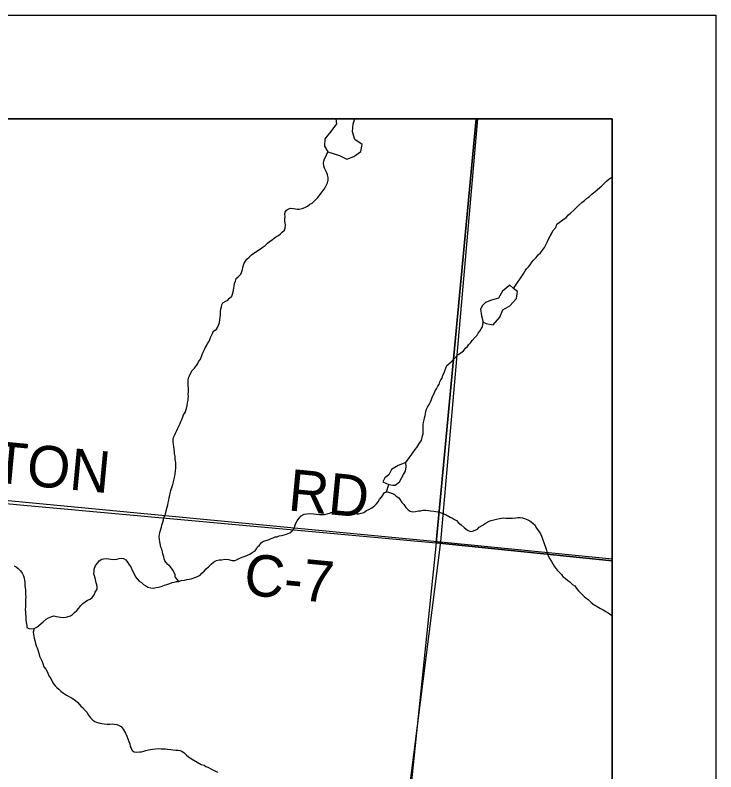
# Model space of a CAD drawing. Extents: x 0 to 34, y -4 to 22.
# Drawn here: x 8.324 to 9, y 20.27 to 21 of the extents above; entities that cross this region are included whole.
import ezdxf

# ---------------------------------------------------------------- set-up
doc = ezdxf.new("R2010")
doc.units = 0
for name, color, linetype in [('GM_X_County_Road', 7, 'Continuous'), ('GM_X_County_Road_Text', 7, 'Continuous'), ('GM_X_Minor_Lake', 7, 'Continuous'), ('GM_X_Minor_River', 7, 'Continuous'), ('GM_X_Section', 7, 'Continuous'), ('GM_X_Township_Road', 7, 'Continuous'), ('SH_Data', 7, 'Continuous'), ('SN_P_Text', 7, 'Continuous')]:
    doc.layers.add(name, color=color, linetype=linetype)

msp = doc.modelspace()

# ---------------------------------------------------------------- linework, layer by layer
at = {"layer": 'GM_X_County_Road'}
msp.add_lwpolyline([(7.2632, 20.63671), (7.3702, 20.62568), (7.41256, 20.62217), (7.42628, 20.62178), (7.44548, 20.62217), (7.45538, 20.62279), (7.4631, 20.62295), (7.47024, 20.62248), (7.47641, 20.62171), (7.48117, 20.62073), (7.4885, 20.61933), (7.50761, 20.61542), (7.52204, 20.61242), (7.53238, 20.61066), (7.54107, 20.60934), (7.55527, 20.60755), (7.58468, 20.60427), (7.63016, 20.59975), (7.68968, 20.59354), (7.69545, 20.59331), (7.82578, 20.57896), (8.73462, 20.49213), (8.9, 20.47558)], dxfattribs=at)
at = {"layer": 'GM_X_Minor_Lake'}
for points in [[(8.63343, 20.9), (8.63402, 20.89516), (8.62876, 20.88779), (8.62296, 20.8807), (8.62252, 20.87375), (8.62587, 20.86831)], [(8.62587, 20.86831), (8.63703, 20.86456), (8.64392, 20.86118), (8.65067, 20.8637), (8.65748, 20.86835), (8.65899, 20.87528), (8.65187, 20.88), (8.64965, 20.88755), (8.65009, 20.89504), (8.65172, 20.9)], [(8.80493, 20.73647), (8.80117, 20.73958), (8.79433, 20.73385), (8.79041, 20.72699), (8.78367, 20.72501), (8.77772, 20.72274)], [(8.7783, 20.70265), (8.78524, 20.70141), (8.79158, 20.70875), (8.79443, 20.71591), (8.80122, 20.7195), (8.80782, 20.72683), (8.80852, 20.73351), (8.80493, 20.73647)], [(8.77772, 20.72274), (8.77498, 20.72013), (8.77301, 20.71643), (8.77393, 20.70998), (8.77565, 20.70378), (8.7783, 20.70265)], [(8.68452, 20.5475), (8.68851, 20.5466), (8.69066, 20.54655), (8.69502, 20.54992), (8.69868, 20.55706), (8.70063, 20.56023), (8.70127, 20.56423), (8.70083, 20.56852), (8.69353, 20.56575), (8.68728, 20.56189), (8.68447, 20.5566), (8.68065, 20.55375)], [(8.68065, 20.55375), (8.67868, 20.54978), (8.68452, 20.5475)]]:
    msp.add_lwpolyline(points, dxfattribs=at)
at = {"layer": 'GM_X_Minor_River'}
for points in [[(8.50755, 20.67923), (8.50868, 20.68106), (8.50982, 20.68317), (8.51095, 20.685), (8.51182, 20.68712), (8.51269, 20.68896), (8.51356, 20.69107), (8.51443, 20.69291), (8.5153, 20.69503), (8.51831, 20.69707), (8.51944, 20.69891), (8.5206, 20.70154), (8.52121, 20.70366), (8.52155, 20.70606), (8.52191, 20.70872), (8.52224, 20.71058), (8.5223, 20.71245), (8.52236, 20.71432), (8.52243, 20.71645), (8.52305, 20.71884), (8.52337, 20.7207), (8.52451, 20.72253), (8.52669, 20.7238), (8.52941, 20.72506), (8.53082, 20.72715), (8.53329, 20.72894), (8.53389, 20.7308), (8.5345, 20.73318), (8.53515, 20.73664), (8.53549, 20.73876), (8.53583, 20.74116), (8.53672, 20.74354), (8.53733, 20.74592), (8.53927, 20.74774), (8.54175, 20.75006), (8.54262, 20.75191), (8.54351, 20.75455), (8.54384, 20.75668), (8.54445, 20.7588), (8.54505, 20.76065), (8.54645, 20.76275), (8.54759, 20.76458), (8.5498, 20.76665), (8.55202, 20.76899), (8.55831, 20.77307), (8.56077, 20.7746), (8.56325, 20.77666), (8.56544, 20.77793), (8.56765, 20.78), (8.56958, 20.78181), (8.57205, 20.78334), (8.57425, 20.78514), (8.57617, 20.78642), (8.57807, 20.78743), (8.58, 20.78897), (8.58167, 20.79079), (8.58387, 20.79259), (8.58447, 20.79444), (8.58484, 20.79764), (8.58463, 20.79952), (8.58417, 20.80167), (8.58423, 20.80354), (8.58457, 20.80567), (8.58437, 20.80781), (8.58471, 20.80994), (8.58584, 20.81177), (8.58776, 20.81332), (8.59019, 20.81378), (8.59259, 20.81344), (8.59446, 20.81311), (8.59632, 20.81279), (8.59819, 20.81273), (8.6009, 20.81345), (8.60361, 20.81443), (8.60606, 20.81569), (8.60827, 20.81776), (8.61071, 20.81876), (8.61265, 20.82057), (8.61458, 20.82238), (8.61598, 20.8242), (8.61794, 20.82655), (8.62018, 20.82969), (8.62213, 20.83203), (8.62355, 20.83439), (8.62442, 20.83624), (8.62529, 20.83835), (8.62591, 20.841), (8.62599, 20.84341), (8.62553, 20.84583), (8.6248, 20.84799), (8.62379, 20.84989), (8.62253, 20.85233), (8.62181, 20.85476), (8.62162, 20.85717), (8.62195, 20.85903), (8.62256, 20.86142), (8.6237, 20.86352), (8.62587, 20.86831)], [(8.80493, 20.73647), (8.81479, 20.75125), (8.8162, 20.75335), (8.81734, 20.75545), (8.81927, 20.75726), (8.82094, 20.75908), (8.82263, 20.7617), (8.82403, 20.76353), (8.8268, 20.76611), (8.82876, 20.76873), (8.8307, 20.77081), (8.83266, 20.77342), (8.83462, 20.77603), (8.83604, 20.77839), (8.83749, 20.78182), (8.83893, 20.78472), (8.84035, 20.78734), (8.84149, 20.78918), (8.84264, 20.79182), (8.8457, 20.7952), (8.84661, 20.79838), (8.85237, 20.80247), (8.85566, 20.80478), (8.85789, 20.80738), (8.8601, 20.80945), (8.86313, 20.81203), (8.86534, 20.8141), (8.86756, 20.81644), (8.8706, 20.81928), (8.87335, 20.82134), (8.87528, 20.82315), (8.87803, 20.8252), (8.88051, 20.82726), (8.88354, 20.82984), (8.88547, 20.83139), (8.88795, 20.83371), (8.88988, 20.83526), (8.89264, 20.83785), (8.89459, 20.83992), (8.89679, 20.84173), (8.89954, 20.84378), (8.9, 20.8441)], [(8.70083, 20.56852), (8.70839, 20.57869), (8.71008, 20.58104), (8.71147, 20.58287), (8.71261, 20.58471), (8.71429, 20.58706), (8.71571, 20.58942), (8.71631, 20.59154), (8.71664, 20.5934), (8.71753, 20.59605), (8.71761, 20.59845), (8.71768, 20.60058), (8.71775, 20.60272), (8.71783, 20.60512), (8.71817, 20.60725), (8.71852, 20.60964), (8.71911, 20.6115), (8.71973, 20.61388), (8.71979, 20.61575), (8.72012, 20.61761), (8.721, 20.61999), (8.72186, 20.62183), (8.72356, 20.62446), (8.72472, 20.62709), (8.7256, 20.62947), (8.72676, 20.63211), (8.72791, 20.63448), (8.72935, 20.63764), (8.73049, 20.63974), (8.73191, 20.6421), (8.73304, 20.64394), (8.73392, 20.64632), (8.73478, 20.64816), (8.73592, 20.65), (8.73681, 20.65264), (8.73796, 20.65501), (8.73855, 20.65686), (8.73971, 20.6595), (8.7406, 20.66214), (8.74474, 20.66576), (8.74751, 20.66861), (8.75, 20.67094), (8.7514, 20.67277), (8.75413, 20.67429), (8.75661, 20.67635), (8.75856, 20.67869), (8.76049, 20.6805), (8.76163, 20.68234), (8.76357, 20.68442), (8.76497, 20.68624), (8.76775, 20.68937), (8.76969, 20.69144), (8.77083, 20.69328), (8.77249, 20.6951), (8.77364, 20.69747), (8.77504, 20.6993), (8.77565, 20.70378)], [(8.48193, 20.45395), (8.47859, 20.45832), (8.47838, 20.4602), (8.47765, 20.46236), (8.47639, 20.4648), (8.47511, 20.46671), (8.4733, 20.46864), (8.47147, 20.47003), (8.46966, 20.47196), (8.46865, 20.47386), (8.46791, 20.47576), (8.46743, 20.47764), (8.46673, 20.4806), (8.46625, 20.48249), (8.46553, 20.48491), (8.46479, 20.48681), (8.4641, 20.4903), (8.46363, 20.49219), (8.46344, 20.4946), (8.46299, 20.49728), (8.46332, 20.49914), (8.46365, 20.501), (8.46456, 20.50418), (8.46516, 20.5063), (8.46576, 20.50816), (8.46666, 20.51107), (8.46726, 20.51319), (8.46759, 20.51505), (8.46819, 20.5169), (8.46905, 20.51874), (8.46996, 20.52192), (8.47089, 20.52563), (8.47149, 20.52775), (8.47182, 20.52961), (8.47244, 20.53227), (8.47279, 20.53466), (8.47341, 20.53705), (8.47373, 20.53891), (8.47436, 20.54156), (8.47495, 20.54341), (8.47556, 20.54553), (8.47616, 20.54738), (8.47677, 20.54977), (8.4771, 20.55163), (8.47771, 20.55402), (8.47831, 20.55587), (8.47864, 20.55773), (8.47874, 20.56066), (8.47908, 20.56306), (8.47915, 20.5652), (8.47898, 20.56814), (8.47878, 20.57002), (8.47857, 20.57189), (8.47839, 20.57457), (8.47794, 20.57726), (8.47773, 20.57913), (8.47753, 20.58101), (8.47708, 20.5837), (8.47689, 20.58611), (8.47643, 20.58826), (8.47651, 20.59093), (8.47684, 20.59279), (8.47771, 20.59464), (8.47885, 20.59674), (8.48001, 20.59937), (8.48116, 20.60174), (8.48202, 20.60359), (8.48345, 20.60622), (8.48405, 20.60807), (8.48492, 20.61018), (8.4858, 20.61256), (8.48666, 20.6144), (8.48808, 20.61676), (8.48868, 20.61861), (8.48928, 20.62073), (8.48991, 20.62339), (8.49053, 20.62604), (8.49088, 20.6287), (8.49094, 20.63057), (8.49127, 20.63243), (8.49107, 20.63431), (8.49141, 20.6367), (8.49121, 20.63858), (8.49128, 20.64071), (8.49108, 20.64286), (8.49088, 20.645), (8.49097, 20.64767), (8.49133, 20.65033), (8.49219, 20.65218), (8.49334, 20.65455), (8.49503, 20.65717), (8.49699, 20.65951), (8.49895, 20.66212), (8.50035, 20.66395), (8.50094, 20.6658), (8.5029, 20.66815), (8.50379, 20.67079), (8.50465, 20.67264), (8.50553, 20.67502), (8.50668, 20.67739), (8.50755, 20.67923)], [(8.68248, 20.54021), (8.68452, 20.5475)], [(8.61213, 20.51913), (8.6148, 20.51878), (8.61773, 20.51842), (8.62014, 20.51835), (8.62255, 20.51828), (8.62525, 20.51899), (8.62823, 20.51997), (8.63041, 20.52097), (8.63283, 20.52116), (8.63577, 20.52107), (8.63871, 20.52072), (8.64111, 20.52038), (8.64351, 20.52003), (8.64644, 20.51968), (8.64831, 20.51935), (8.65098, 20.51927), (8.65366, 20.51919), (8.65553, 20.51913), (8.65796, 20.51959), (8.66039, 20.52031), (8.66314, 20.52237), (8.66531, 20.5231), (8.66804, 20.52489), (8.67078, 20.52667), (8.67273, 20.52875), (8.67439, 20.53057), (8.67554, 20.53294), (8.67749, 20.53528), (8.67863, 20.53712), (8.68031, 20.53947), (8.68248, 20.54021), (8.68434, 20.53988), (8.6862, 20.53929), (8.68805, 20.5387), (8.6899, 20.53784), (8.69172, 20.53618), (8.69408, 20.53451), (8.69536, 20.5326), (8.69715, 20.53014), (8.69895, 20.52794), (8.70101, 20.52521), (8.70308, 20.523), (8.70517, 20.5216), (8.70757, 20.521), (8.71025, 20.52118), (8.71322, 20.52189), (8.7151, 20.5221), (8.7178, 20.52255), (8.72021, 20.52248), (8.72288, 20.52239), (8.72475, 20.52207), (8.72795, 20.5217), (8.72982, 20.52138), (8.73168, 20.52105), (8.73513, 20.51988), (8.73777, 20.51899), (8.73989, 20.51813), (8.74383, 20.51587), (8.74594, 20.51473), (8.74778, 20.51361), (8.74988, 20.51247), (8.75143, 20.51055), (8.7543, 20.50833), (8.75717, 20.50583), (8.7603, 20.50333), (8.76348, 20.50217), (8.76536, 20.50238), (8.7678, 20.50337), (8.76998, 20.50437), (8.77165, 20.50619), (8.77464, 20.5077), (8.77657, 20.50924), (8.77849, 20.51052), (8.78148, 20.51203), (8.78338, 20.51278), (8.78581, 20.51323), (8.78851, 20.51395), (8.79121, 20.51467), (8.7931, 20.51488), (8.79525, 20.51508), (8.79739, 20.51501), (8.79926, 20.51496), (8.8014, 20.51489), (8.80354, 20.51482), (8.80704, 20.51525), (8.80892, 20.51546), (8.81134, 20.51565), (8.81346, 20.51505), (8.81532, 20.51446), (8.8185, 20.51329), (8.8206, 20.51216), (8.82349, 20.5102), (8.82556, 20.50827), (8.8263, 20.5061), (8.82886, 20.50255), (8.83091, 20.49982), (8.83191, 20.49765), (8.83239, 20.49576), (8.83313, 20.49387), (8.83412, 20.49143), (8.83486, 20.48954)], [(8.40278, 20.45051), (8.40231, 20.45266), (8.40161, 20.45562), (8.40066, 20.4594), (8.40019, 20.46128), (8.40026, 20.46342), (8.40034, 20.46582), (8.40152, 20.46925), (8.40375, 20.47186), (8.40515, 20.47369), (8.40761, 20.47521), (8.4095, 20.47569), (8.41192, 20.47588), (8.41459, 20.47553), (8.41646, 20.47547), (8.41939, 20.47512), (8.42208, 20.4753), (8.42452, 20.47603), (8.42693, 20.47622), (8.4288, 20.47589), (8.4309, 20.47476), (8.43243, 20.47231), (8.43423, 20.46985), (8.43577, 20.46793), (8.43676, 20.46549), (8.43827, 20.46251), (8.44028, 20.45844), (8.44182, 20.45652), (8.44389, 20.45405), (8.44599, 20.45292), (8.4478, 20.45099), (8.45017, 20.44958), (8.45227, 20.44818), (8.45493, 20.44756), (8.4576, 20.44748), (8.46003, 20.44794), (8.46245, 20.4484), (8.46489, 20.44913), (8.46814, 20.45036), (8.47057, 20.45082), (8.47328, 20.45181), (8.47573, 20.4528), (8.47762, 20.45328), (8.47978, 20.45374), (8.48193, 20.45395), (8.48436, 20.45467), (8.48759, 20.45511), (8.48975, 20.45557), (8.49191, 20.45604), (8.49407, 20.45651), (8.49732, 20.45774), (8.50003, 20.45873), (8.50249, 20.45999), (8.50415, 20.46181), (8.50636, 20.46388), (8.50831, 20.46596), (8.51052, 20.46803), (8.51328, 20.47061), (8.51549, 20.47241), (8.51848, 20.47393), (8.52092, 20.47465), (8.52333, 20.47484), (8.52656, 20.47528), (8.53004, 20.47517), (8.53349, 20.474), (8.53591, 20.47419), (8.5378, 20.47466), (8.5408, 20.47644), (8.54324, 20.47717), (8.54595, 20.47815), (8.54812, 20.47916), (8.55057, 20.48015), (8.55276, 20.48169), (8.5555, 20.48347), (8.5569, 20.4853), (8.55803, 20.48713), (8.5597, 20.48895), (8.56165, 20.4913), (8.56384, 20.49257), (8.56736, 20.49379), (8.56925, 20.49427), (8.57116, 20.49528), (8.57306, 20.49602), (8.57496, 20.49676), (8.57684, 20.49697), (8.57874, 20.49772), (8.5809, 20.49818), (8.5836, 20.4989), (8.58576, 20.49937), (8.58903, 20.50087), (8.59123, 20.50268), (8.59346, 20.50528), (8.59405, 20.50713), (8.59466, 20.50925), (8.5961, 20.51241), (8.59778, 20.5145), (8.60001, 20.5171), (8.603, 20.51861), (8.60543, 20.51907), (8.60811, 20.51926), (8.61213, 20.51913)], [(8.83486, 20.48954), (8.83558, 20.48684), (8.83655, 20.48388), (8.83727, 20.48145), (8.83825, 20.47848), (8.83977, 20.47576), (8.84155, 20.47303), (8.84282, 20.47086), (8.84409, 20.46868), (8.84691, 20.46485), (8.84898, 20.46265), (8.85105, 20.46045), (8.85284, 20.45799), (8.85469, 20.45713), (8.8573, 20.45491), (8.85913, 20.45352), (8.86173, 20.45103), (8.86382, 20.44963), (8.86562, 20.44717), (8.86741, 20.44471), (8.87027, 20.44195), (8.87312, 20.43919), (8.87495, 20.4378), (8.87678, 20.4364), (8.87964, 20.43364), (8.88278, 20.43141), (8.88567, 20.42972), (8.88882, 20.42775), (8.89119, 20.42634), (8.89382, 20.42492), (8.89618, 20.42351), (8.89932, 20.42128), (8.9, 20.42074)], [(8.32328, 20.469), (8.32512, 20.46788), (8.32721, 20.46621), (8.32928, 20.46401), (8.33108, 20.46181), (8.33233, 20.4591), (8.3328, 20.45695), (8.33327, 20.45506), (8.33347, 20.45292), (8.33364, 20.44998), (8.33384, 20.44783), (8.33403, 20.44569), (8.33424, 20.44381), (8.33417, 20.44168), (8.33435, 20.439), (8.33427, 20.4366), (8.33417, 20.43339), (8.33411, 20.43152), (8.33403, 20.42912), (8.33396, 20.42725), (8.33414, 20.42431), (8.33407, 20.42244), (8.33453, 20.42002), (8.33443, 20.41708), (8.33488, 20.4144), (8.33532, 20.41144), (8.33553, 20.40957), (8.33736, 20.40844), (8.33976, 20.4081), (8.34246, 20.40855), (8.34491, 20.40981), (8.34683, 20.41109), (8.34932, 20.41342), (8.35124, 20.41496), (8.35401, 20.41755), (8.35646, 20.41881), (8.35945, 20.42005), (8.36134, 20.42053), (8.36401, 20.42018), (8.368, 20.41952), (8.37067, 20.41917), (8.37336, 20.41936), (8.37525, 20.4201), (8.37742, 20.42083), (8.37934, 20.42211), (8.38127, 20.42392), (8.38375, 20.42598), (8.38543, 20.42807), (8.38739, 20.43068), (8.38933, 20.43249), (8.39153, 20.43429), (8.39399, 20.43582), (8.39643, 20.43681), (8.39836, 20.43836), (8.40032, 20.44097), (8.40148, 20.4436), (8.40318, 20.44649), (8.40324, 20.44836), (8.40278, 20.45051)], [(8.34246, 20.40855), (8.34153, 20.40484), (8.34174, 20.40296), (8.34242, 20.3992), (8.34314, 20.39677), (8.34386, 20.39408), (8.34458, 20.39165), (8.34532, 20.38976), (8.34606, 20.38787), (8.34703, 20.38463), (8.34774, 20.38194), (8.34848, 20.37978), (8.34974, 20.37733), (8.35072, 20.37463), (8.35196, 20.37165), (8.35375, 20.36919), (8.35526, 20.36621), (8.35676, 20.36295), (8.35855, 20.36022), (8.36056, 20.35616), (8.3626, 20.35315), (8.36442, 20.35149), (8.36625, 20.34983), (8.36833, 20.3479), (8.37095, 20.34622), (8.37383, 20.34426), (8.37725, 20.34228), (8.3791, 20.34142), (8.38223, 20.33892), (8.38458, 20.33698), (8.38741, 20.33368), (8.38924, 20.33229), (8.39183, 20.32954), (8.39338, 20.32762), (8.39489, 20.3249), (8.39669, 20.32244), (8.39902, 20.31996), (8.40086, 20.31884), (8.4027, 20.31798), (8.40589, 20.31708), (8.40775, 20.31676), (8.41015, 20.31641), (8.41283, 20.31633), (8.41551, 20.31625), (8.41792, 20.31644), (8.41979, 20.31612), (8.42219, 20.31577), (8.42457, 20.3149), (8.42642, 20.31404), (8.42847, 20.31131), (8.43049, 20.3075), (8.432, 20.30452), (8.43299, 20.30208), (8.43371, 20.29965), (8.4347, 20.29722), (8.43516, 20.2948), (8.4359, 20.29291), (8.43717, 20.29073), (8.43901, 20.2896), (8.44168, 20.28926), (8.44409, 20.28945), (8.44598, 20.28966), (8.44813, 20.29012), (8.4503, 20.29086), (8.45273, 20.29132), (8.4565, 20.292), (8.45946, 20.29245), (8.46268, 20.29261), (8.46483, 20.29255), (8.46697, 20.29248), (8.46911, 20.29242), (8.47124, 20.29208), (8.47417, 20.29172), (8.47631, 20.29139), (8.47924, 20.29103), (8.48112, 20.29098), (8.48298, 20.29065), (8.48484, 20.29006), (8.4872, 20.28865), (8.48927, 20.28645), (8.49136, 20.28478), (8.49319, 20.28339), (8.49581, 20.2817), (8.49976, 20.27944), (8.50371, 20.27745), (8.50636, 20.27657), (8.5082, 20.27544), (8.51005, 20.27458), (8.51347, 20.27288), (8.5169, 20.27117), (8.51926, 20.26976)]]:
    msp.add_lwpolyline(points, dxfattribs=at)
at = {"layer": 'GM_X_Section'}
for points in [[(8.76866, 20.9), (8.08305, 20.9), (8.0438, 20.5539), (8.73019, 20.4912)], [(8.9, 20.47381), (8.9, 20.9), (8.76866, 20.9), (8.73019, 20.4912)], [(8.0438, 20.5539), (8.73019, 20.4912), (8.66411, 19.85205), (7.97405, 19.91801)], [(8.9, 19.82975), (8.9, 20.47381), (8.73019, 20.4912), (8.66411, 19.85205)]]:
    msp.add_lwpolyline(points, close=True, dxfattribs=at)
at = {"layer": 'GM_X_Township_Road'}
msp.add_line((8.73462, 20.49213), (8.77048, 20.9), dxfattribs=at)
msp.add_lwpolyline([(8.62507, 19.46888), (8.65806, 19.80297), (8.67815, 20.01586), (8.69801, 20.20289), (8.73462, 20.49213)], dxfattribs=at)
at = {"layer": 'SH_Data'}
for p, q in [((2, 21), (9, 21)), ((9, 21), (9, 14)), ((2.1, 20.9), (8.9, 20.9)), ((8.9, 20.9), (8.9, 14.1))]:
    msp.add_line(p, q, dxfattribs=at)
at = {"layer": 'SN_P_Text'}
msp.add_lwpolyline([(8.9, 14.1), (8.9, 20.9), (2.1, 20.9), (2.1, 14.1)], close=True, dxfattribs=at)

# ---------------------------------------------------------------- texts
at = {"layer": 'GM_X_County_Road_Text'}
for s, rotation, p in [('WILMINGTON', 354.5796, (8.06789, 20.57179)), ('RD', 354.53716, (8.58651, 20.52249)), ('C-7', 354.47201, (8.5437, 20.44118))]:
    msp.add_text(s, height=0.04, rotation=rotation, dxfattribs=at).set_placement(p)

doc.saveas('drawing.dxf')
